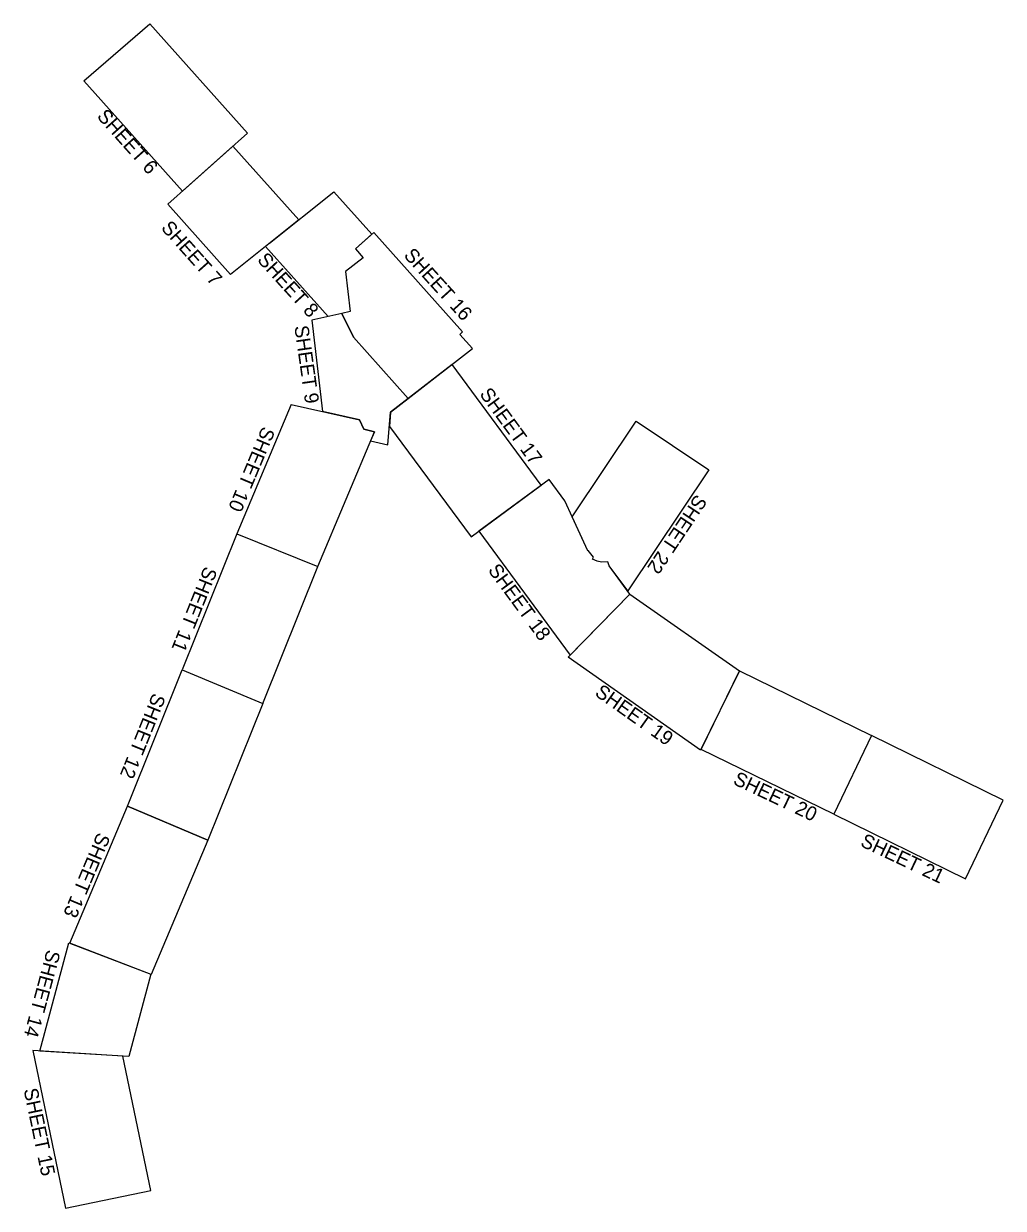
# Model space of a CAD drawing. Extents: x 1965738 to 1975720, y 789514 to 801591.
import ezdxf

# ---------------------------------------------------------------- set-up
doc = ezdxf.new("R2010")
doc.units = 0
doc.layers.add('RD_SHT_ShtClip', color=7, linetype='Continuous')
doc.layers.add('RD_SHT_TX', color=7, linetype='Continuous')

msp = doc.modelspace()

# ---------------------------------------------------------------- linework, layer by layer
at = {"layer": 'RD_SHT_ShtClip'}
for p, q in [((1966351, 801007), (1967023, 801591)), ((1967023, 801591), (1968019, 800476)), ((1967355, 799883), (1966351, 801007)), ((1968019, 800476), (1967355, 799883)), ((1968242, 799352), (1968899, 799877)), ((1968899, 799877), (1969285, 799444)), ((1969304, 799461), (1969118, 799295)), ((1969285, 799444), (1969118, 799295)), ((1970209, 798450), (1969306, 799462)), ((1968841, 798606), (1968202, 799321)), ((1969118, 799295), (1969198, 799205)), ((1969118, 799295), (1969198, 799205)), ((1969198, 799205), (1969018, 799066)), ((1969198, 799205), (1969018, 799066)), ((1969018, 799066), (1969066, 798658)), ((1969018, 799066), (1969066, 798658)), ((1969018, 799066), (1969066, 798658)), ((1968979, 798638), (1968673, 798567)), ((1968673, 798567), (1968782, 797639)), ((1969066, 798658), (1968979, 798638)), ((1969097, 798394), (1968979, 798638)), ((1968979, 798638), (1969097, 798394)), ((1969097, 798394), (1968979, 798638)), ((1970181, 798424), (1970209, 798450)), ((1969655, 797769), (1969097, 798394)), ((1969097, 798394), (1969655, 797769)), ((1969655, 797769), (1969097, 798394)), ((1970312, 798278), (1970181, 798424)), ((1969655, 797769), (1970312, 798278)), ((1970105, 798118), (1969476, 797631)), ((1971012, 796887), (1970105, 798118)), ((1968463, 797710), (1967909, 796390)), ((1968463, 797710), (1969160, 797554)), ((1969476, 797631), (1969655, 797769)), ((1968782, 797639), (1969158, 797554)), ((1969450, 797298), (1969476, 797631)), ((1969476, 797631), (1969465, 797486)), ((1969160, 797554), (1969204, 797456)), ((1969465, 797486), (1970296, 796359)), ((1968736, 796058), (1969311, 797431)), ((1969204, 797456), (1969311, 797431)), ((1969311, 797431), (1969272, 797338)), ((1969272, 797338), (1969450, 797298)), ((1970296, 796359), (1971012, 796887)), ((1967910, 796389), (1967353, 795004)), ((1967909, 796390), (1968736, 796058)), ((1968173, 794659), (1968735, 796058)), ((1971285, 795132), (1971916, 795776)), ((1971916, 795776), (1973032, 794993)), ((1972636, 794183), (1971285, 795132)), ((1967353, 795004), (1968173, 794659)), ((1973032, 794993), (1972636, 794183))]:
    msp.add_line(p, q, dxfattribs=at)
for points in [[(1967870, 800342), (1968541, 799591), (1967844, 799035), (1967206, 799750)], [(1971893, 795809), (1971703, 796065), (1971689, 796106), (1971625, 796102), (1971580, 796112), (1971534, 796131), (1971543, 796151), (1971489, 796221), (1971485, 796217), (1971327, 796563), (1971980, 797539), (1972720, 797044)], [(1970375, 796417), (1971306, 795154), (1971916, 795776), (1971703, 796065), (1971689, 796106), (1971625, 796102), (1971580, 796112), (1971534, 796131), (1971543, 796151), (1971489, 796221), (1971485, 796217), (1971252, 796728), (1971091, 796945)], [(1968173, 794659), (1967614, 793267), (1966794, 793613), (1967353, 795004)], [(1973032, 794992), (1974376, 794334), (1973992, 793532), (1972641, 794193)], [(1974376, 794334), (1973992, 793532), (1975336, 792874), (1975720, 793676)], [(1967038, 791899), (1966206, 792217), (1966794, 793613), (1967614, 793267)], [(1967034, 791900), (1966809, 791062), (1965902, 791116), (1966199, 792220)], [(1966749, 791066), (1965829, 791121), (1966162, 789514), (1967033, 789694)]]:
    msp.add_lwpolyline(points, close=True, dxfattribs=at)
msp.add_lwpolyline([(1969311, 797431), (1969204, 797456), (1969160, 797554), (1968782, 797639)], dxfattribs=at)

# ---------------------------------------------------------------- texts
at = {"layer": 'RD_SHT_TX'}
for s, rotation, p in [('SHEET 6', 311.7606, (1966476, 800642)), ('SHEET 7', 311.7606, (1967130, 799504)), ('SHEET 16', 312.235, (1969603, 799224)), ('SHEET 8', 312.235, (1968110, 799178)), ('SHEET 9', 278.0544, (1968495, 798505)), ('SHEET 17', 306.3161, (1970377, 797814)), ('SHEET 10', 247.246, (1968171, 797493)), ('SHEET 22', 236.294, (1972591, 796802)), ('SHEET 11', 248.119, (1967581, 796067)), ('SHEET 18', 306.3161, (1970463, 796019)), ('SHEET 19', 324.6777, (1971548, 794749)), ('SHEET 12', 248.119, (1967055, 794776)), ('SHEET 20', 334.6352, (1972957, 793843)), ('SHEET 13', 247.1375, (1966492, 793354)), ('SHEET 21', 334.6352, (1974254, 793211)), ('SHEET 14', 254.9393, (1965975, 792158)), ('SHEET 15', 281.7118, (1965736, 790724))]:
    msp.add_text(s, height=144, rotation=rotation, dxfattribs=at).set_placement(p)

doc.saveas('drawing.dxf')
